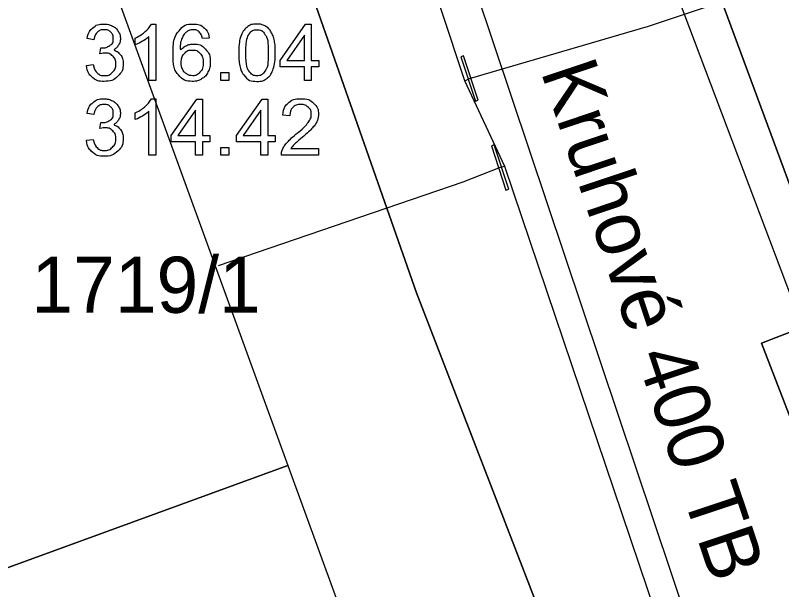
# Model space of a CAD drawing. Extents: x -562248 to -562040, y -1079385 to -1079027.
# Drawn here: x -562123.63 to -562103.13, y -1079190.52 to -1079175.15 of the extents above; entities that cross this region are included whole.
import ezdxf

# ---------------------------------------------------------------- set-up
doc = ezdxf.new("R2010")
doc.units = 0
for name, color, linetype in [('Armatura vodovodní', 7, 'Continuous'), ('Kanalizační stoka', 7, 'Continuous'), ('Parcela-polygon', 7, 'Continuous'), ('Parcela-text', 7, 'Continuous'), ('Popis kmenové stoky', 7, 'Continuous'), ('Popis šachty', 7, 'Continuous'), ('Vodovodní přípojka', 7, 'Continuous'), ('Vodovodní řad', 7, 'Continuous')]:
    doc.layers.add(name, color=color, linetype=linetype)

msp = doc.modelspace()

# ---------------------------------------------------------------- linework, layer by layer
at = {"layer": 'Armatura vodovodní'}
for points in [[(-562111.321, -1079177.449), (-562111.246, -1079177.425), (-562111.64, -1079176.238), (-562111.714, -1079176.263)], [(-562110.506, -1079179.828), (-562110.432, -1079179.803), (-562110.822, -1079178.616), (-562110.897, -1079178.64)]]:
    msp.add_lwpolyline(points, close=True, dxfattribs=at)
at = {"layer": 'Kanalizační stoka'}
for points in [[(-562098.95, -1079211.35), (-562123.19, -1079139.07)], [(-562108.95, -1079166.63), (-562107.34, -1079170.89), (-562101.716, -1079185.754), (-562101.215, -1079187.021), (-562096.915, -1079198.445), (-562094.443, -1079204.981), (-562093.91, -1079206.39)]]:
    msp.add_lwpolyline(points, dxfattribs=at)
at = {"layer": 'Parcela-polygon'}
for points in [[(-562074.7, -1079253.09), (-562081.96, -1079237.32), (-562088.81, -1079221.44), (-562094.66, -1079207.06), (-562098.96, -1079196.12), (-562103.67, -1079183.92), (-562101.64, -1079183.14), (-562108.26, -1079165.24), (-562109.03, -1079162.72), (-562110.57, -1079158.43), (-562113.13, -1079150.92), (-562115.47, -1079143.79), (-562118.94, -1079132.53), (-562120.22, -1079128.2), (-562121.94, -1079119.29), (-562122.55, -1079115.89), (-562122.79, -1079112.89), (-562122.92, -1079108.96), (-562122.69, -1079105.05), (-562122.05, -1079101.16)], [(-562130.204, -1079213.482), (-562129.52, -1079213.24), (-562126.56, -1079212.06), (-562110.18, -1079204.89), (-562109.412, -1079204.67), (-562108.694, -1079204.319), (-562108.049, -1079203.848), (-562107.496, -1079203.271), (-562107.054, -1079202.606), (-562106.734, -1079201.874), (-562106.547, -1079201.097), (-562106.5, -1079200.3), (-562107.01, -1079197.84), (-562112.9, -1079182.58), (-562117.83, -1079168.5), (-562124.14, -1079150.14), (-562125.7, -1079148.16), (-562127.71, -1079147.6), (-562130.14, -1079147.9), (-562151.942, -1079151.733)], [(-562151.942, -1079151.733), (-562130.14, -1079147.9), (-562127.71, -1079147.6), (-562125.7, -1079148.16), (-562124.14, -1079150.14), (-562117.83, -1079168.5), (-562112.9, -1079182.58), (-562107.01, -1079197.84), (-562106.5, -1079200.3), (-562100.28, -1079214.7), (-562095.19, -1079227.16), (-562092.25, -1079234.14), (-562087.93, -1079243.96)], [(-562081.378, -1079153.144), (-562109.03, -1079162.72), (-562108.26, -1079165.24), (-562101.64, -1079183.14), (-562103.67, -1079183.92), (-562098.96, -1079196.12), (-562094.66, -1079207.06), (-562088.81, -1079221.44), (-562081.96, -1079237.32), (-562074.7, -1079253.09), (-562050.734, -1079242.89)], [(-562121.43, -1079173.64), (-562121.29, -1079173.59), (-562116.34, -1079187.19), (-562111.38, -1079200.8), (-562120.46, -1079204.1), (-562125.42, -1079190.5), (-562130.38, -1079176.88), (-562121.43, -1079173.64)]]:
    msp.add_lwpolyline(points, dxfattribs=at)
for points in [[(-562130.38, -1079176.88), (-562121.43, -1079173.64), (-562121.29, -1079173.59), (-562116.34, -1079187.19), (-562125.42, -1079190.5)], [(-562116.34, -1079187.19), (-562111.38, -1079200.8), (-562120.46, -1079204.1), (-562125.42, -1079190.5)]]:
    msp.add_lwpolyline(points, close=True, dxfattribs=at)
at = {"layer": 'Popis šachty'}
for points in [[(-562119.991, -1079175.388), (-562119.873, -1079175.388), (-562119.873, -1079176.894)], [(-562115.899, -1079176.894), (-562115.899, -1079176.535), (-562116.549, -1079176.535), (-562116.549, -1079176.365), (-562115.866, -1079175.394), (-562115.715, -1079175.394), (-562115.715, -1079176.365), (-562115.512, -1079176.365), (-562115.512, -1079176.535), (-562115.715, -1079176.535), (-562115.715, -1079176.894), (-562115.899, -1079176.894)], [(-562121.527, -1079175.81), (-562121.711, -1079175.777)], [(-562120.425, -1079175.942), (-562120.425, -1079175.764)], [(-562119.873, -1079176.894), (-562120.057, -1079176.894), (-562120.057, -1079175.72)], [(-562118.444, -1079175.762), (-562118.627, -1079175.777)], [(-562115.899, -1079176.365), (-562115.899, -1079175.688), (-562116.368, -1079176.365), (-562115.899, -1079176.365)], [(-562121.366, -1079176.182), (-562121.346, -1079176.021)], [(-562121.729, -1079176.496), (-562121.545, -1079176.472)], [(-562118.133, -1079176.894), (-562118.133, -1079176.684), (-562117.923, -1079176.684), (-562117.923, -1079176.894), (-562118.133, -1079176.894)], [(-562119.991, -1079177.388), (-562119.873, -1079177.388), (-562119.873, -1079178.894)], [(-562118.811, -1079178.894), (-562118.811, -1079178.535), (-562119.461, -1079178.535), (-562119.461, -1079178.365), (-562118.778, -1079177.394), (-562118.627, -1079177.394), (-562118.627, -1079178.365), (-562118.424, -1079178.365), (-562118.424, -1079178.535), (-562118.627, -1079178.535), (-562118.627, -1079178.894), (-562118.811, -1079178.894)], [(-562117.064, -1079178.894), (-562117.064, -1079178.535), (-562117.714, -1079178.535), (-562117.714, -1079178.365), (-562117.031, -1079177.394), (-562116.88, -1079177.394), (-562116.88, -1079178.365), (-562116.677, -1079178.365), (-562116.677, -1079178.535), (-562116.88, -1079178.535), (-562116.88, -1079178.894), (-562117.064, -1079178.894)], [(-562119.873, -1079178.894), (-562120.057, -1079178.894), (-562120.057, -1079177.72)], [(-562118.811, -1079178.365), (-562118.811, -1079177.688), (-562119.28, -1079178.365), (-562118.811, -1079178.365)], [(-562117.064, -1079178.365), (-562117.064, -1079177.688), (-562117.533, -1079178.365), (-562117.064, -1079178.365)], [(-562121.527, -1079177.81), (-562121.711, -1079177.777)], [(-562120.425, -1079177.942), (-562120.425, -1079177.764)], [(-562116.289, -1079177.841), (-562116.478, -1079177.821)], [(-562121.366, -1079178.182), (-562121.346, -1079178.021)], [(-562121.729, -1079178.496), (-562121.545, -1079178.472)], [(-562118.133, -1079178.894), (-562118.133, -1079178.684), (-562117.923, -1079178.684), (-562117.923, -1079178.894), (-562118.133, -1079178.894)], [(-562115.521, -1079178.716), (-562115.521, -1079178.894), (-562116.513, -1079178.894)], [(-562116.257, -1079178.716), (-562115.521, -1079178.716)]]:
    msp.add_lwpolyline(points, dxfattribs=at)
for points in [[(-562121.711, -1079175.777), (-562121.677, -1079175.591), (-562121.558, -1079175.49), (-562121.438, -1079175.388), (-562121.26, -1079175.388), (-562121.137, -1079175.388), (-562121.033, -1079175.44), (-562120.93, -1079175.493), (-562120.875, -1079175.584), (-562120.821, -1079175.675), (-562120.821, -1079175.777), (-562120.821, -1079175.874), (-562120.873, -1079175.954), (-562120.925, -1079176.033), (-562121.027, -1079176.08), (-562120.894, -1079176.111), (-562120.821, -1079176.208), (-562120.747, -1079176.304), (-562120.747, -1079176.449), (-562120.747, -1079176.646), (-562120.891, -1079176.782), (-562121.034, -1079176.919), (-562121.253, -1079176.919), (-562121.45, -1079176.919), (-562121.581, -1079176.801), (-562121.711, -1079176.683), (-562121.729, -1079176.496)], [(-562120.425, -1079175.764), (-562120.271, -1079175.692), (-562120.155, -1079175.588), (-562120.039, -1079175.485), (-562119.991, -1079175.388)], [(-562118.627, -1079175.777), (-562118.651, -1079175.667), (-562118.696, -1079175.618), (-562118.771, -1079175.539), (-562118.881, -1079175.539), (-562118.969, -1079175.539), (-562119.036, -1079175.588), (-562119.123, -1079175.651), (-562119.173, -1079175.773), (-562119.224, -1079175.895), (-562119.226, -1079176.12), (-562119.159, -1079176.019), (-562119.063, -1079175.97), (-562118.966, -1079175.921), (-562118.861, -1079175.921), (-562118.677, -1079175.921), (-562118.547, -1079176.056), (-562118.417, -1079176.192), (-562118.417, -1079176.406), (-562118.417, -1079176.547), (-562118.478, -1079176.669), (-562118.539, -1079176.79), (-562118.646, -1079176.854), (-562118.752, -1079176.919), (-562118.887, -1079176.919), (-562119.118, -1079176.919), (-562119.263, -1079176.749), (-562119.409, -1079176.58), (-562119.409, -1079176.192), (-562119.409, -1079175.757), (-562119.248, -1079175.56), (-562119.107, -1079175.388), (-562118.87, -1079175.388), (-562118.693, -1079175.388), (-562118.579, -1079175.487), (-562118.466, -1079175.587), (-562118.444, -1079175.762)], [(-562117.654, -1079176.154), (-562117.654, -1079175.888), (-562117.599, -1079175.725), (-562117.544, -1079175.563), (-562117.436, -1079175.475), (-562117.328, -1079175.388), (-562117.165, -1079175.388), (-562117.044, -1079175.388), (-562116.953, -1079175.436), (-562116.862, -1079175.485), (-562116.803, -1079175.576), (-562116.744, -1079175.668), (-562116.71, -1079175.799), (-562116.676, -1079175.931), (-562116.676, -1079176.154), (-562116.676, -1079176.418), (-562116.73, -1079176.58), (-562116.785, -1079176.742), (-562116.892, -1079176.831), (-562117, -1079176.919), (-562117.165, -1079176.919), (-562117.382, -1079176.919), (-562117.505, -1079176.764), (-562117.654, -1079176.576), (-562117.654, -1079176.154)], [(-562121.346, -1079176.021), (-562121.328, -1079176.023), (-562121.316, -1079176.023), (-562121.199, -1079176.023), (-562121.104, -1079175.962), (-562121.01, -1079175.901), (-562121.01, -1079175.773), (-562121.01, -1079175.672), (-562121.079, -1079175.605), (-562121.147, -1079175.539), (-562121.256, -1079175.539), (-562121.363, -1079175.539), (-562121.435, -1079175.606), (-562121.507, -1079175.674), (-562121.527, -1079175.81)], [(-562117.464, -1079176.154), (-562117.464, -1079176.524), (-562117.378, -1079176.646), (-562117.291, -1079176.768), (-562117.165, -1079176.768), (-562117.038, -1079176.768), (-562116.952, -1079176.645), (-562116.866, -1079176.523), (-562116.866, -1079176.154), (-562116.866, -1079175.783), (-562116.952, -1079175.662), (-562117.038, -1079175.54), (-562117.167, -1079175.54), (-562117.293, -1079175.54), (-562117.369, -1079175.647), (-562117.464, -1079175.784), (-562117.464, -1079176.154)], [(-562120.057, -1079175.72), (-562120.123, -1079175.784), (-562120.231, -1079175.847), (-562120.339, -1079175.911), (-562120.425, -1079175.942)], [(-562119.197, -1079176.407), (-562119.197, -1079176.503), (-562119.157, -1079176.59), (-562119.116, -1079176.677), (-562119.044, -1079176.722), (-562118.972, -1079176.768), (-562118.891, -1079176.768), (-562118.774, -1079176.768), (-562118.691, -1079176.674), (-562118.607, -1079176.579), (-562118.607, -1079176.418), (-562118.607, -1079176.262), (-562118.69, -1079176.172), (-562118.772, -1079176.083), (-562118.899, -1079176.083), (-562119.023, -1079176.083), (-562119.11, -1079176.172), (-562119.197, -1079176.262), (-562119.197, -1079176.407)], [(-562121.545, -1079176.472), (-562121.514, -1079176.628), (-562121.438, -1079176.697), (-562121.362, -1079176.767), (-562121.252, -1079176.767), (-562121.121, -1079176.767), (-562121.032, -1079176.677), (-562120.943, -1079176.587), (-562120.943, -1079176.454), (-562120.943, -1079176.327), (-562121.026, -1079176.244), (-562121.109, -1079176.162), (-562121.236, -1079176.162), (-562121.289, -1079176.162), (-562121.366, -1079176.182)], [(-562121.711, -1079177.777), (-562121.677, -1079177.591), (-562121.558, -1079177.49), (-562121.438, -1079177.388), (-562121.26, -1079177.388), (-562121.137, -1079177.388), (-562121.033, -1079177.44), (-562120.93, -1079177.493), (-562120.875, -1079177.584), (-562120.821, -1079177.675), (-562120.821, -1079177.777), (-562120.821, -1079177.874), (-562120.873, -1079177.954), (-562120.925, -1079178.033), (-562121.027, -1079178.08), (-562120.894, -1079178.111), (-562120.821, -1079178.208), (-562120.747, -1079178.304), (-562120.747, -1079178.449), (-562120.747, -1079178.646), (-562120.891, -1079178.782), (-562121.034, -1079178.919), (-562121.253, -1079178.919), (-562121.45, -1079178.919), (-562121.581, -1079178.801), (-562121.711, -1079178.683), (-562121.729, -1079178.496)], [(-562120.425, -1079177.764), (-562120.271, -1079177.692), (-562120.155, -1079177.588), (-562120.039, -1079177.485), (-562119.991, -1079177.388)], [(-562116.478, -1079177.821), (-562116.459, -1079177.61), (-562116.332, -1079177.499), (-562116.205, -1079177.388), (-562115.991, -1079177.388), (-562115.775, -1079177.388), (-562115.65, -1079177.507), (-562115.524, -1079177.627), (-562115.524, -1079177.804), (-562115.524, -1079177.894), (-562115.56, -1079177.981), (-562115.597, -1079178.068), (-562115.683, -1079178.164), (-562115.768, -1079178.26), (-562115.966, -1079178.428), (-562116.132, -1079178.567), (-562116.179, -1079178.617), (-562116.226, -1079178.666), (-562116.257, -1079178.716)], [(-562121.346, -1079178.021), (-562121.328, -1079178.023), (-562121.316, -1079178.023), (-562121.199, -1079178.023), (-562121.104, -1079177.962), (-562121.01, -1079177.901), (-562121.01, -1079177.773), (-562121.01, -1079177.672), (-562121.079, -1079177.605), (-562121.147, -1079177.539), (-562121.256, -1079177.539), (-562121.363, -1079177.539), (-562121.435, -1079177.606), (-562121.507, -1079177.674), (-562121.527, -1079177.81)], [(-562120.057, -1079177.72), (-562120.123, -1079177.784), (-562120.231, -1079177.847), (-562120.339, -1079177.911), (-562120.425, -1079177.942)], [(-562116.513, -1079178.894), (-562116.515, -1079178.827), (-562116.491, -1079178.765), (-562116.453, -1079178.664), (-562116.37, -1079178.566), (-562116.286, -1079178.468), (-562116.129, -1079178.339), (-562115.885, -1079178.138), (-562115.799, -1079178.021), (-562115.713, -1079177.904), (-562115.713, -1079177.8), (-562115.713, -1079177.69), (-562115.792, -1079177.615), (-562115.87, -1079177.54), (-562115.995, -1079177.54), (-562116.128, -1079177.54), (-562116.208, -1079177.62), (-562116.288, -1079177.699), (-562116.289, -1079177.841)], [(-562121.545, -1079178.472), (-562121.514, -1079178.628), (-562121.438, -1079178.697), (-562121.362, -1079178.767), (-562121.252, -1079178.767), (-562121.121, -1079178.767), (-562121.032, -1079178.677), (-562120.943, -1079178.587), (-562120.943, -1079178.454), (-562120.943, -1079178.327), (-562121.026, -1079178.244), (-562121.109, -1079178.162), (-562121.236, -1079178.162), (-562121.289, -1079178.162), (-562121.366, -1079178.182)]]:
    msp.add_open_spline(points, degree=3, dxfattribs=at)
at = {"layer": 'Vodovodní přípojka'}
for points in [[(-562111.609, -1079176.901), (-562111.481, -1079176.844), (-562106.696, -1079175.445), (-562099.788, -1079173.136)], [(-562110.54, -1079179.194), (-562110.665, -1079179.222), (-562111.658, -1079179.618), (-562118.2, -1079181.85)]]:
    msp.add_lwpolyline(points, dxfattribs=at)
at = {"layer": 'Vodovodní řad'}
msp.add_lwpolyline([(-562104.508, -1079195.68), (-562105.675, -1079193.599), (-562106.045, -1079192.495), (-562108.292, -1079185.845), (-562110.54, -1079179.194), (-562111.609, -1079176.901), (-562113.474, -1079171.283), (-562115.559, -1079165.192), (-562118.308, -1079157.281), (-562119.874, -1079152.505), (-562123.128, -1079142.718), (-562124.818, -1079137.317), (-562126.048, -1079133.176), (-562126.972, -1079129.683), (-562127.886, -1079125.317), (-562128.484, -1079121.808), (-562129.183, -1079117.074), (-562129.389, -1079112.24), (-562129.474, -1079106.997), (-562129.319, -1079103.524), (-562128.819, -1079100.288), (-562128.175, -1079096.35), (-562128.115, -1079096.032)], dxfattribs=at)

# ---------------------------------------------------------------- texts
at = {"layer": 'Parcela-text'}
msp.add_text('1719/1', height=1.5, dxfattribs=at).set_placement((-562123.2, -1079183.11))
at = {"layer": 'Popis kmenové stoky'}
msp.add_text('Kruhové 400 TB', height=1.5, rotation=288.5395, dxfattribs=at).set_placement((-562109.585, -1079176.649))

doc.saveas('drawing.dxf')
